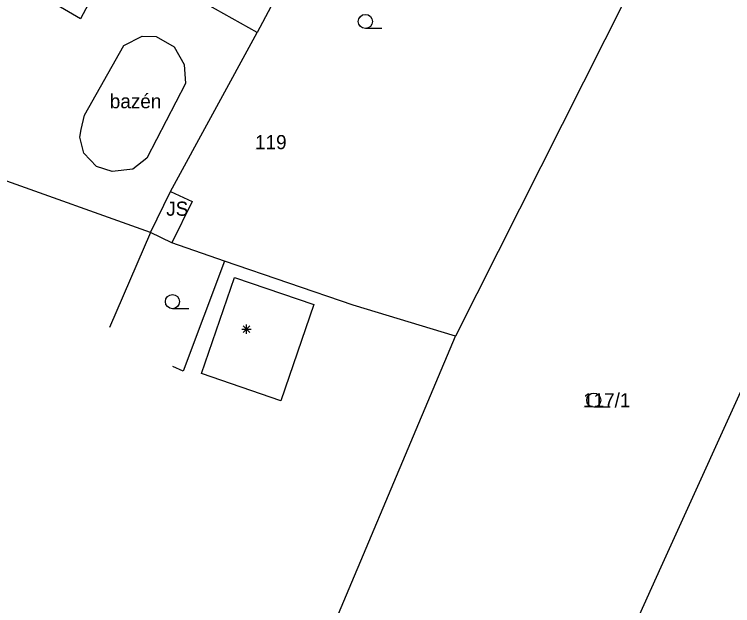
# Model space of a CAD drawing. Extents: x -836568 to -836015, y -1070547 to -1070212.
# Drawn here: x -836498.92 to -836460.84, y -1070392.19 to -1070360.84 of the extents above; entities that cross this region are included whole.
import ezdxf

# ---------------------------------------------------------------- set-up
doc = ezdxf.new("R2010")
doc.units = 0
for name, color, linetype in [('BodPole_mer', 7, 'Continuous'), ('Budovy_hranice', 7, 'Continuous'), ('Budovy_kody', 7, 'Continuous'), ('OstPloch_kody', 7, 'Continuous'), ('RuianPar_popis', 7, 'Continuous'), ('Stavby_hr_stav', 7, 'Continuous'), ('Stavby_kody', 7, 'Continuous'), ('Stavby_linie', 7, 'Continuous'), ('Vodstvo_hranice', 7, 'Continuous'), ('Vodstvo_kody', 7, 'Continuous')]:
    doc.layers.add(name, color=color, linetype=linetype)

msp = doc.modelspace()

# ---------------------------------------------------------------- linework, layer by layer
at = {"layer": 'BodPole_mer'}
for p, q in [((-836495.41, -1070361.07), (-836495.41, -1070361.07)), ((-836492.15, -1070362), (-836492.15, -1070362)), ((-836491.4, -1070362.02), (-836491.4, -1070362.02)), ((-836486.05, -1070361.8), (-836486.05, -1070361.8)), ((-836493.11, -1070362.5), (-836493.11, -1070362.5)), ((-836490.44, -1070362.57), (-836490.44, -1070362.57)), ((-836489.91, -1070363.49), (-836489.91, -1070363.49)), ((-836489.84, -1070364.5), (-836489.84, -1070364.5)), ((-836495.21, -1070366.18), (-836495.21, -1070366.18)), ((-836495.38, -1070366.95), (-836495.38, -1070366.95)), ((-836495.45, -1070367.35), (-836495.45, -1070367.35)), ((-836495.24, -1070368.2), (-836495.24, -1070368.2)), ((-836491.89, -1070368.47), (-836491.89, -1070368.47)), ((-836494.57, -1070368.91), (-836494.57, -1070368.91)), ((-836493.74, -1070369.18), (-836493.74, -1070369.18)), ((-836492.64, -1070369.05), (-836492.64, -1070369.05)), ((-836490.64, -1070370.23), (-836490.64, -1070370.23)), ((-836489.5, -1070370.76), (-836489.5, -1070370.76)), ((-836491.71, -1070372.41), (-836491.71, -1070372.41)), ((-836490.58, -1070372.96), (-836490.58, -1070372.96)), ((-836487.78, -1070373.92), (-836487.78, -1070373.92)), ((-836487.25, -1070374.79), (-836487.25, -1070374.79)), ((-836483.05, -1070376.23), (-836483.05, -1070376.23)), ((-836480.96, -1070376.27), (-836480.96, -1070376.27)), ((-836475.54, -1070377.9), (-836475.54, -1070377.9)), ((-836484.8, -1070381.33), (-836484.8, -1070381.33)), ((-836464.64, -1070390.16), (-836464.64, -1070390.16))]:
    msp.add_line(p, q, dxfattribs=at)
at = {"layer": 'Budovy_hranice'}
for q in [(-836506.52, -1070367.12), (-836493.88, -1070377.44)]:
    msp.add_line((-836491.71, -1070372.41), q, dxfattribs=at)
for points in [[(-836486.05, -1070361.8), (-836493.56, -1070357.58), (-836495.41, -1070361.07), (-836497.11, -1070360.09), (-836496.94, -1070359.76), (-836500.13, -1070357.99), (-836498.52, -1070354.78), (-836498.99, -1070354.52), (-836494.45, -1070346.05), (-836491.04, -1070347.91), (-836489.68, -1070345.25), (-836482.72, -1070349.16), (-836484.08, -1070351.72), (-836481.46, -1070353.16), (-836481.83, -1070353.85), (-836486.05, -1070361.8)], [(-836483.05, -1070376.23), (-836484.8, -1070381.33), (-836489, -1070379.89), (-836487.25, -1070374.79), (-836483.05, -1070376.23)]]:
    msp.add_lwpolyline(points, dxfattribs=at)
at = {"layer": 'Budovy_kody'}
for p, q in [((-836486.433, -1070377.707), (-836486.787, -1070377.353)), ((-836486.433, -1070377.353), (-836486.787, -1070377.707)), ((-836486.61, -1070377.78), (-836486.61, -1070377.28)), ((-836486.86, -1070377.53), (-836486.36, -1070377.53))]:
    msp.add_line(p, q, dxfattribs=at)
at = {"layer": 'OstPloch_kody'}
for p, q in [((-836479.435, -1070361.59), (-836480.31, -1070361.59)), ((-836489.665, -1070376.45), (-836490.54, -1070376.45)), ((-836467.325, -1070381.67), (-836468.2, -1070381.67))]:
    msp.add_line(p, q, dxfattribs=at)
for centre in [(-836480.31, -1070361.215), (-836490.54, -1070376.075), (-836468.2, -1070381.295)]:
    msp.add_ellipse(centre, major_axis=(0.375, 0), ratio=0.999999, dxfattribs=at)
at = {"layer": 'RuianPar_popis'}
for p, q in [((-836486.16, -1070367.99), (-836486.16, -1070367.99)), ((-836468.77, -1070381.68), (-836468.77, -1070381.68))]:
    msp.add_line(p, q, dxfattribs=at)
at = {"layer": 'Stavby_hr_stav'}
msp.add_lwpolyline([(-836491.71, -1070372.41), (-836490.64, -1070370.23), (-836489.5, -1070370.76), (-836490.58, -1070372.96), (-836491.71, -1070372.41)], dxfattribs=at)
at = {"layer": 'Stavby_linie'}
for p, q in [((-836464.69, -1070356.37), (-836475.54, -1070377.9)), ((-836490.64, -1070370.23), (-836486.05, -1070361.8))]:
    msp.add_line(p, q, dxfattribs=at)
for points in [[(-836451.09, -1070365.35), (-836457.52, -1070375.69), (-836459.45, -1070378.71), (-836464.64, -1070390.16), (-836469.09, -1070399.98), (-836470.4, -1070403.24)], [(-836483.68, -1070397.24), (-836475.54, -1070377.9), (-836480.96, -1070376.27), (-836487.78, -1070373.92), (-836490.58, -1070372.96)], [(-836487.78, -1070373.92), (-836489.97, -1070379.76), (-836490.52, -1070379.52)]]:
    msp.add_lwpolyline(points, dxfattribs=at)
at = {"layer": 'Vodstvo_hranice'}
msp.add_lwpolyline([(-836495.38, -1070366.95), (-836495.21, -1070366.18), (-836493.11, -1070362.5), (-836492.15, -1070362), (-836491.4, -1070362.02), (-836490.44, -1070362.57), (-836489.91, -1070363.49), (-836489.84, -1070364.5), (-836491.89, -1070368.47), (-836492.64, -1070369.05), (-836493.74, -1070369.18), (-836494.57, -1070368.91), (-836495.24, -1070368.2), (-836495.45, -1070367.35), (-836495.38, -1070366.95)], dxfattribs=at)

# ---------------------------------------------------------------- texts
at = {"layer": 'RuianPar_popis'}
for s, p in [('119', (-836486.16, -1070367.99)), ('117/1', (-836468.77, -1070381.68))]:
    msp.add_text(s, height=0.75, dxfattribs=at).set_placement(p)
at = {"layer": 'Stavby_kody'}
msp.add_text('JS', height=0.75, dxfattribs=at).set_placement((-836490.87, -1070371.52))
at = {"layer": 'Vodstvo_kody'}
msp.add_text('bazén', height=0.75, dxfattribs=at).set_placement((-836493.86, -1070365.82))

doc.saveas('drawing.dxf')
